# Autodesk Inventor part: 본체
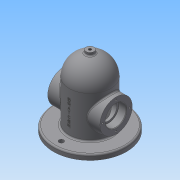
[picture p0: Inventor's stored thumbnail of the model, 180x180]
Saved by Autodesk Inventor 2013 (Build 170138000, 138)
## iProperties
Created: 2019-11
Part Number: 본체
Material: Generic
Document SubType Name: Modeling
Designer: Administrator
Density: 1 g/cm^3
Author: Administrator
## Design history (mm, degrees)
sketch "스케치1"
  geometry: C1 r 70 at (0, 0); 1 further point
  constraints: 1 centre point, 1 coincident
  dimensions: "d0" = 140 diameter of C1
extrude "돌출1" new body sketch "스케치1" distance "d2" = 10; taper "d3" = 0 deg
sketch "스케치2"
  geometry: L1 (0, 0)-(0, 55); L2 (0, 0)-(0, -55); C1 r 70 at (0, 0) reference; C2 r 4.5 at (0, 55); C3 r 4.5 at (0, -55); A1 r 55 centre (0, 0) between (0, 55) and (0, -55)
  constraints: 4 end point, 3 centre point, 3 coincident, 2 point on circle, 1 collinear, 1 vertical
  dimensions: "d4" = 110 diameter of A1; "d5" = 9 diameter of C2; "d6" = 9 diameter of C3
extrude "돌출2" cut sketch "스케치2" stored distance "d7" = 10; taper "d8" = 0 deg
sketch "스케치3"
  geometry: L1 (70, 10)-(-70, 10) reference; L2 (-70, 0)-(70, 0) reference; L3 (0, 10)-(0, 130); L4 (-40, 90)-(-40, 10); L5 (0, 10)-(-40, 10); A1 r 40 centre (0, 90) between (0, 130) and (-40, 90); 1 further point
  constraints: 6 end point, 3 perpendicular, 2 point on circle, 2 point on line, 1 centre point, 1 midpoint, 1 tangent
  dimensions: "d11" = 130 distance of L3.end point (0, 0); "d12" = 80 diameter of A1
revolve "회전1" sketch "스케치3" stored, may be unused: angle "d13" = 90 deg
node "작업 평면1"
sketch "스케치4"
  geometry: C1 r 40 at (0, 0) reference; C2 r 7.5 at (0, 0); 1 further point
  constraints: 1 centre point, 1 coincident
  dimensions: "d15" = 15 diameter of C2
extrude "돌출3" join sketch "스케치4" stored distance "d16" = 10; taper "d17" = 0 deg
sketch "스케치5"
  geometry: L1 (70, 10)-(-70, 10) reference; L2 (-70, 0)-(70, 0) reference; L3 (40, 90)-(-40, 90) reference; L4 (-40, 10)-(40, 10) reference; L5 (-7.5, 129.291)-(7.5, 129.291) reference; L6 (40, 90)-(-40, 90) reference; L7 (-7.5, 135)-(7.5, 135) reference; L8 (-7.5, 129.291)-(7.5, 129.291) reference; L9 (-40, 10)-(-40, 90) reference; L10 (40, 10)-(40, 90) reference; L11 (0, 0)-(0, 120); L12 (-30, 90)-(-30, 0); L13 (0, 0)-(-30, 0); A1 r 30 centre (0, 90) between (0, 120) and (-30, 90); 3 further points
  constraints: 6 end point, 2 parallel, 2 point on circle, 2 point on line, 1 centre point, 1 coincident, 1 perpendicular, 1 tangent, 1 other
  dimensions: "d18" = 60 diameter of A1
revolve "회전2" sketch "스케치5" stored, may be unused: angle "d19" = 90 deg
node "작업 평면2"
sketch "스케치6"
  geometry: L1 (40, 90)-(-40, 90) reference; L2 (-40, 10)-(40, 10) reference; L3 (-70, 0)-(70, 0) reference; C1 r 31 at (0, 50); 1 further point
  constraints: 1 centre point, 1 vertical alignment
  dimensions: "d21" = 62 diameter of C1; "d22" = 50 distance from line of C1.centre L3
extrude "돌출4" join sketch "스케치6" stored distance "d23" = 10; taper "d24" = 0 deg
sketch "스케치7"
  geometry: C1 r 31 at (0, 0) reference; C2 r 20 at (0, 0); 1 further point
  constraints: 1 centre point, 1 coincident
  dimensions: "d25" = 40 diameter of C2
extrude "돌출5" cut sketch "스케치7" distance "d26" = 15; taper "d27" = 0 deg
sketch "스케치8"
  geometry: C1 r 20 at (0, 0) reference; C2 r 16.5 at (0, 0); 1 further point
  constraints: 1 centre point, 1 coincident
  dimensions: "d28" = 33 diameter of C2
extrude "돌출6" cut sketch "스케치8" stored distance "d29" = 15; taper "d30" = 0 deg
sketch "스케치9" dims "d31" = 52
  geometry: L1 (0, 0)-(-26, 0); C1 r 31 at (0, 0) reference; 2 further points
  constraints: 2 coincident, 2 end point, 1 horizontal, 1 horizontal alignment, 2 other
hole "구멍1" sketch "스케치9" at (-26, 0) diameter "d33" = 3.242; stored, may be unused: countersink angle "d37" = 90 deg, drill point angle "d39" = 118 deg; dims "d34" = 8, "d35" = 4, "d36" = 2, "d38" = 10
sketch "스케치10"
  geometry: 1 further point
node "작업 평면3"
sketch "스케치11"
  geometry: C1 r 7.5 at (0, 0) reference; 1 further point
  constraints: 1 coincident
hole "구멍2" sketch "스케치11" at (0, 0) diameter "d44" = 5.188; stored, may be unused: countersink angle "d48" = 90 deg, drill point angle "d50" = 118 deg; dims "d45" = 8, "d46" = 4, "d47" = 2, "d49" = 10
node "작업 평면4"
sketch "스케치12"
  geometry: L1 (-70, 0)-(70, 0) reference; 2 further points
  constraints: 1 vertical alignment, 1 other
  dimensions: "d52" = 50 distance from line of point (0, 50) L1
extrude "돌출8" join sketch "스케치12" distance "d55" = 0.5; taper "d56" = 0 deg
fillet "모깎기1" dims "d57" = 3
fillet "모깎기2" dims "d58" = 3
fillet "모깎기3" dims "d59" = 3
chamfer "모따기1" distance "d60" = 1; stored, may be unused: second distance "d61" = 2, angle "d62" = 45 deg
fillet "모깎기4" dims "d63" = 0.3
node "솔리드1"
pattern_circular "원형 패턴1" dims angle "d41" = 360 deg
mirror "대칭1"
node "투영된 루프1"
node "투영된 루프2"
node "투영된 루프3"
node "투영된 루프4"
node "투영된 루프5"
node "투영된 루프6"
node "투영된 루프7"
other parameters: "d14" = 135
